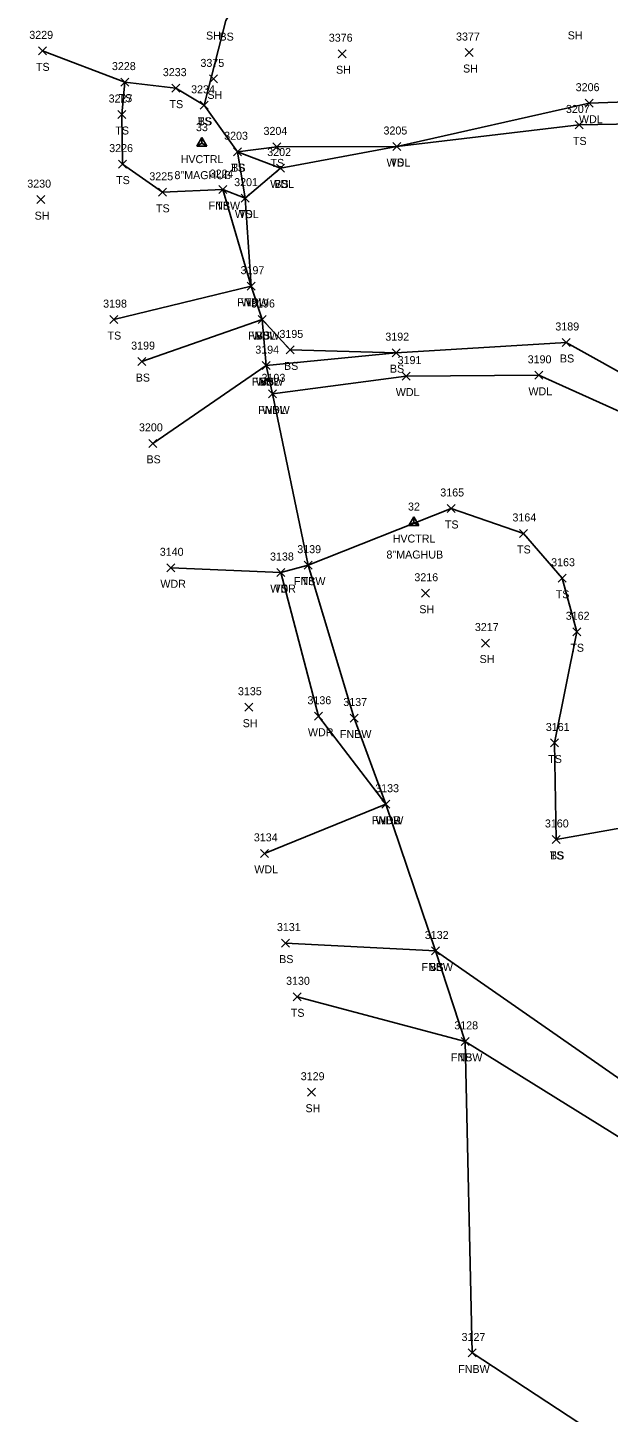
# Model space of a CAD drawing. Extents: x 1601151 to 1602912, y 499508 to 501770.
# Drawn here: x 1601337 to 1601482.2, y 500250.6 to 500596.8 of the extents above; entities that cross this region are included whole.
import ezdxf

# ---------------------------------------------------------------- set-up
doc = ezdxf.new("R2010")
doc.units = 0
for name, color, linetype in [('C_A', 7, 'Continuous'), ('C_C', 7, 'Continuous'), ('C_I', 7, 'Continuous'), ('CPSM', 7, 'Continuous'), ('L_A', 7, 'Continuous'), ('L_I', 7, 'Continuous'), ('L_TIC', 7, 'Continuous'), ('LAWA', 7, 'Continuous'), ('LELB', 7, 'Continuous'), ('LFNC', 7, 'Continuous')]:
    doc.layers.add(name, color=color, linetype=linetype)

msp = doc.modelspace()

# ---------------------------------------------------------------- linework, layer by layer
at = {"layer": 'CPSM'}
for p, q in [((1601379.29, 500567.21), (1601380.54, 500569.37)), ((1601381.79, 500567.21), (1601380.54, 500569.37)), ((1601380.54, 500567.93), (1601380.54, 500569.37)), ((1601379.29, 500567.21), (1601380.54, 500567.93)), ((1601379.29, 500567.21), (1601381.79, 500567.21)), ((1601380.54, 500567.93), (1601380.54, 500567.93)), ((1601380.54, 500567.93), (1601381.79, 500567.21)), ((1601432.31, 500472.36), (1601433.56, 500474.52)), ((1601432.31, 500472.36), (1601433.56, 500473.08)), ((1601432.31, 500472.36), (1601434.81, 500472.36)), ((1601434.81, 500472.36), (1601433.56, 500474.52)), ((1601433.56, 500473.08), (1601433.56, 500474.52)), ((1601433.56, 500473.08), (1601433.56, 500473.08)), ((1601433.56, 500473.08), (1601434.81, 500472.36))]:
    msp.add_line(p, q, dxfattribs=at)
at = {"layer": 'L_TIC'}
for points in [[(1601339.66, 500590), (1601341.66, 500592)], [(1601341.66, 500590), (1601339.66, 500592)], [(1601414.61, 500589.29), (1601416.61, 500591.29)], [(1601416.61, 500589.29), (1601414.61, 500591.29)], [(1601446.36, 500589.58), (1601448.36, 500591.58)], [(1601448.36, 500589.58), (1601446.36, 500591.58)], [(1601360.32, 500582.19), (1601362.32, 500584.19)], [(1601362.32, 500582.19), (1601360.32, 500584.19)], [(1601360.32, 500582.19), (1601362.32, 500584.19)], [(1601362.32, 500582.19), (1601360.32, 500584.19)], [(1601373.04, 500580.68), (1601375.04, 500582.68)], [(1601375.04, 500580.68), (1601373.04, 500582.68)], [(1601382.45, 500582.99), (1601384.45, 500584.99)], [(1601384.45, 500582.99), (1601382.45, 500584.99)], [(1601476.41, 500576.92), (1601478.41, 500578.92)], [(1601478.41, 500576.92), (1601476.41, 500578.92)], [(1601359.5, 500574.09), (1601361.5, 500576.09)], [(1601361.5, 500574.09), (1601359.5, 500576.09)], [(1601380.12, 500576.39), (1601382.12, 500578.39)], [(1601382.12, 500576.39), (1601380.12, 500578.39)], [(1601380.12, 500576.39), (1601382.12, 500578.39)], [(1601382.12, 500576.39), (1601380.12, 500578.39)], [(1601473.92, 500571.48), (1601475.92, 500573.48)], [(1601475.92, 500571.48), (1601473.92, 500573.48)], [(1601388.46, 500564.78), (1601390.46, 500566.78)], [(1601390.46, 500564.78), (1601388.46, 500566.78)], [(1601388.46, 500564.78), (1601390.46, 500566.78)], [(1601390.46, 500564.78), (1601388.46, 500566.78)], [(1601398.3, 500565.99), (1601400.3, 500567.99)], [(1601400.3, 500565.99), (1601398.3, 500567.99)], [(1601428.3, 500566.09), (1601430.3, 500568.09)], [(1601430.3, 500566.09), (1601428.3, 500568.09)], [(1601428.3, 500566.09), (1601430.3, 500568.09)], [(1601430.3, 500566.09), (1601428.3, 500568.09)], [(1601359.7, 500561.69), (1601361.7, 500563.69)], [(1601361.7, 500561.69), (1601359.7, 500563.69)], [(1601399.22, 500560.71), (1601401.22, 500562.71)], [(1601401.22, 500560.71), (1601399.22, 500562.71)], [(1601399.22, 500560.71), (1601401.22, 500562.71)], [(1601401.22, 500560.71), (1601399.22, 500562.71)], [(1601339.24, 500552.81), (1601341.24, 500554.81)], [(1601341.24, 500552.81), (1601339.24, 500554.81)], [(1601369.67, 500554.64), (1601371.67, 500556.64)], [(1601371.67, 500554.64), (1601369.67, 500556.64)], [(1601384.76, 500555.32), (1601386.76, 500557.32)], [(1601386.76, 500555.32), (1601384.76, 500557.32)], [(1601384.76, 500555.32), (1601386.76, 500557.32)], [(1601386.76, 500555.32), (1601384.76, 500557.32)], [(1601390.39, 500553.19), (1601392.39, 500555.19)], [(1601392.39, 500553.19), (1601390.39, 500555.19)], [(1601390.39, 500553.19), (1601392.39, 500555.19)], [(1601392.39, 500553.19), (1601390.39, 500555.19)], [(1601391.91, 500531.17), (1601393.91, 500533.17)], [(1601393.91, 500531.17), (1601391.91, 500533.17)], [(1601391.91, 500531.17), (1601393.91, 500533.17)], [(1601393.91, 500531.17), (1601391.91, 500533.17)], [(1601391.91, 500531.17), (1601393.91, 500533.17)], [(1601393.91, 500531.17), (1601391.91, 500533.17)], [(1601357.55, 500522.82), (1601359.55, 500524.82)], [(1601359.55, 500522.82), (1601357.55, 500524.82)], [(1601394.61, 500522.84), (1601396.61, 500524.84)], [(1601396.61, 500522.84), (1601394.61, 500524.84)], [(1601394.61, 500522.84), (1601396.61, 500524.84)], [(1601396.61, 500522.84), (1601394.61, 500524.84)], [(1601394.61, 500522.84), (1601396.61, 500524.84)], [(1601396.61, 500522.84), (1601394.61, 500524.84)], [(1601401.63, 500515.24), (1601403.63, 500517.24)], [(1601403.63, 500515.24), (1601401.63, 500517.24)], [(1601428.12, 500514.55), (1601430.12, 500516.55)], [(1601430.12, 500514.55), (1601428.12, 500516.55)], [(1601470.63, 500517.1), (1601472.63, 500519.1)], [(1601472.63, 500517.1), (1601470.63, 500519.1)], [(1601364.57, 500512.32), (1601366.57, 500514.32)], [(1601366.57, 500512.32), (1601364.57, 500514.32)], [(1601395.59, 500511.31), (1601397.59, 500513.31)], [(1601397.59, 500511.31), (1601395.59, 500513.31)], [(1601395.59, 500511.31), (1601397.59, 500513.31)], [(1601397.59, 500511.31), (1601395.59, 500513.31)], [(1601395.59, 500511.31), (1601397.59, 500513.31)], [(1601397.59, 500511.31), (1601395.59, 500513.31)], [(1601430.61, 500508.7), (1601432.61, 500510.7)], [(1601432.61, 500508.7), (1601430.61, 500510.7)], [(1601463.79, 500508.89), (1601465.79, 500510.89)], [(1601465.79, 500508.89), (1601463.79, 500510.89)], [(1601397.17, 500504.26), (1601399.17, 500506.26)], [(1601399.17, 500504.26), (1601397.17, 500506.26)], [(1601397.17, 500504.26), (1601399.17, 500506.26)], [(1601399.17, 500504.26), (1601397.17, 500506.26)], [(1601367.25, 500491.88), (1601369.25, 500493.88)], [(1601369.25, 500491.88), (1601367.25, 500493.88)], [(1601441.9, 500475.6), (1601443.9, 500477.6)], [(1601443.9, 500475.6), (1601441.9, 500477.6)], [(1601441.9, 500475.6), (1601443.9, 500477.6)], [(1601443.9, 500475.6), (1601441.9, 500477.6)], [(1601459.94, 500469.36), (1601461.94, 500471.36)], [(1601461.94, 500469.36), (1601459.94, 500471.36)], [(1601371.8, 500460.77), (1601373.8, 500462.77)], [(1601373.8, 500460.77), (1601371.8, 500462.77)], [(1601399.29, 500459.59), (1601401.29, 500461.59)], [(1601401.29, 500459.59), (1601399.29, 500461.59)], [(1601399.29, 500459.59), (1601401.29, 500461.59)], [(1601401.29, 500459.59), (1601399.29, 500461.59)], [(1601406.1, 500461.43), (1601408.1, 500463.43)], [(1601408.1, 500461.43), (1601406.1, 500463.43)], [(1601406.1, 500461.43), (1601408.1, 500463.43)], [(1601408.1, 500461.43), (1601406.1, 500463.43)], [(1601469.62, 500458.16), (1601471.62, 500460.16)], [(1601471.62, 500458.16), (1601469.62, 500460.16)], [(1601435.43, 500454.41), (1601437.43, 500456.41)], [(1601437.43, 500454.41), (1601435.43, 500456.41)], [(1601450.5, 500441.96), (1601452.5, 500443.96)], [(1601452.5, 500441.96), (1601450.5, 500443.96)], [(1601473.27, 500444.78), (1601475.27, 500446.78)], [(1601475.27, 500444.78), (1601473.27, 500446.78)], [(1601391.27, 500425.92), (1601393.27, 500427.92)], [(1601393.27, 500425.92), (1601391.27, 500427.92)], [(1601408.7, 500423.66), (1601410.7, 500425.66)], [(1601410.7, 500423.66), (1601408.7, 500425.66)], [(1601417.6, 500423.22), (1601419.6, 500425.22)], [(1601419.6, 500423.22), (1601417.6, 500425.22)], [(1601467.73, 500416.98), (1601469.73, 500418.98)], [(1601469.73, 500416.98), (1601467.73, 500418.98)], [(1601425.58, 500401.67), (1601427.58, 500403.67)], [(1601427.58, 500401.67), (1601425.58, 500403.67)], [(1601425.58, 500401.67), (1601427.58, 500403.67)], [(1601427.58, 500401.67), (1601425.58, 500403.67)], [(1601425.58, 500401.67), (1601427.58, 500403.67)], [(1601427.58, 500401.67), (1601425.58, 500403.67)], [(1601468.15, 500392.86), (1601470.15, 500394.86)], [(1601470.15, 500392.86), (1601468.15, 500394.86)], [(1601468.15, 500392.86), (1601470.15, 500394.86)], [(1601470.15, 500392.86), (1601468.15, 500394.86)], [(1601395.23, 500389.38), (1601397.23, 500391.38)], [(1601397.23, 500389.38), (1601395.23, 500391.38)], [(1601400.43, 500366.95), (1601402.43, 500368.95)], [(1601402.43, 500366.95), (1601400.43, 500368.95)], [(1601437.99, 500364.98), (1601439.99, 500366.98)], [(1601439.99, 500364.98), (1601437.99, 500366.98)], [(1601437.99, 500364.98), (1601439.99, 500366.98)], [(1601439.99, 500364.98), (1601437.99, 500366.98)], [(1601403.37, 500353.52), (1601405.37, 500355.52)], [(1601405.37, 500353.52), (1601403.37, 500355.52)], [(1601445.35, 500342.38), (1601447.35, 500344.38)], [(1601447.35, 500342.38), (1601445.35, 500344.38)], [(1601445.35, 500342.38), (1601447.35, 500344.38)], [(1601447.35, 500342.38), (1601445.35, 500344.38)], [(1601406.97, 500329.67), (1601408.97, 500331.67)], [(1601408.97, 500329.67), (1601406.97, 500331.67)], [(1601447.17, 500264.48), (1601449.17, 500266.48)], [(1601449.17, 500264.48), (1601447.17, 500266.48)]]:
    msp.add_lwpolyline(points, dxfattribs=at)
at = {"layer": 'LAWA'}
for points in [[(1601544.34, 500325.67), (1601519.22, 500363.44), (1601505.75, 500400.34), (1601520.62, 500411.67), (1601500.1, 500494.02), (1601464.79, 500509.89), (1601431.61, 500509.7), (1601398.17, 500505.26), (1601396.59, 500512.31), (1601395.61, 500523.84), (1601392.91, 500532.17), (1601391.39, 500554.19), (1601400.22, 500561.71), (1601429.3, 500567.09), (1601477.41, 500577.92), (1601523.77, 500579.55), (1601560.2, 500571.77), (1601556.37, 500545), (1601575.25, 500522.25), (1601572.33, 500557.32), (1601570.48, 500566.05)], [(1601426.58, 500402.67), (1601409.7, 500424.66), (1601400.29, 500460.59), (1601372.8, 500461.77)], [(1601426.58, 500402.67), (1601396.23, 500390.38)]]:
    msp.add_lwpolyline(points, dxfattribs=at)
at = {"layer": 'LELB'}
for points in [[(1601400.22, 500561.71), (1601389.46, 500565.78), (1601381.12, 500577.39), (1601386.5, 500598.56), (1601395.6, 500613.55), (1601414.62, 500625.07), (1601439.1, 500619.46), (1601474.92, 500625.17)], [(1601385.76, 500556.32), (1601370.67, 500555.64), (1601360.7, 500562.69), (1601360.5, 500575.09), (1601361.32, 500583.19), (1601340.66, 500591)], [(1601361.32, 500583.19), (1601374.04, 500581.68), (1601381.12, 500577.39)], [(1601391.39, 500554.19), (1601389.46, 500565.78), (1601399.3, 500566.99), (1601429.3, 500567.09), (1601474.92, 500572.48), (1601521.56, 500573.33), (1601560.2, 500571.77), (1601571.6, 500572.54), (1601583.23, 500572.75), (1601587.85, 500570.12), (1601597.03, 500565.28), (1601591.65, 500558.79)], [(1601391.39, 500554.19), (1601385.76, 500556.32)], [(1601392.91, 500532.17), (1601358.55, 500523.82)], [(1601402.63, 500516.24), (1601395.61, 500523.84), (1601365.57, 500513.32)], [(1601505.75, 500400.34), (1601529.2, 500405.62), (1601546.77, 500411.94), (1601552.89, 500447.21), (1601530.6, 500483.27), (1601555.01, 500494.39), (1601547.11, 500513.14), (1601509.53, 500496.99), (1601471.63, 500518.1), (1601429.12, 500515.55), (1601396.59, 500512.31), (1601368.25, 500492.88)], [(1601402.63, 500516.24), (1601429.12, 500515.55)], [(1601400.29, 500460.59), (1601407.1, 500462.43), (1601442.9, 500476.6)], [(1601469.15, 500393.86), (1601468.73, 500417.98), (1601474.27, 500445.78), (1601470.62, 500459.16), (1601460.94, 500470.36), (1601442.9, 500476.6)], [(1601505.75, 500400.34), (1601469.15, 500393.86)], [(1601401.43, 500367.95), (1601438.99, 500365.98), (1601491.06, 500329.76), (1601544.34, 500325.67)], [(1601608.13, 500275.28), (1601543.25, 500306.85), (1601488.66, 500317.14), (1601446.35, 500343.38), (1601404.37, 500354.52)]]:
    msp.add_lwpolyline(points, dxfattribs=at)
at = {"layer": 'LFNC'}
msp.add_lwpolyline([(1601630.4, 500172), (1601539.57, 500215.59), (1601496.11, 500234.02), (1601448.17, 500265.48), (1601446.35, 500343.38), (1601438.99, 500365.98), (1601426.58, 500402.67), (1601418.6, 500424.22), (1601407.1, 500462.43), (1601398.17, 500505.26), (1601396.59, 500512.31), (1601395.61, 500523.84), (1601392.91, 500532.17), (1601385.76, 500556.32)], dxfattribs=at)

# ---------------------------------------------------------------- texts
at = {"layer": 'C_A'}
for p in [(1601375.24, 500562.93), (1601428.25, 500468.08)]:
    msp.add_text('HVCTRL', height=2, dxfattribs=at).set_placement(p)
at = {"layer": 'C_C'}
for p in [(1601373.69, 500558.93), (1601426.7, 500464.08)]:
    msp.add_text('8"MAGHUB', height=2, dxfattribs=at).set_placement(p)
at = {"layer": 'C_I'}
for s, p in [('33', (1601379.08, 500570.93)), ('32', (1601432.09, 500476.08))]:
    msp.add_text(s, height=2, dxfattribs=at).set_placement(p)
at = {"layer": 'L_A'}
for s, p in [('SH', (1601472.01, 500593.87)), ('SH', (1601381.58, 500593.82)), ('BS', (1601384.95, 500593.56)), ('TS', (1601339.07, 500586)), ('SH', (1601414.09, 500585.29)), ('SH', (1601445.85, 500585.58)), ('TS', (1601359.73, 500578.19)), ('TS', (1601359.73, 500578.19)), ('TS', (1601372.45, 500576.68)), ('SH', (1601381.94, 500578.99)), ('TS', (1601358.91, 500570.09)), ('TS', (1601379.53, 500572.39)), ('BS', (1601379.56, 500572.39)), ('WDL', (1601474.83, 500572.92)), ('TS', (1601473.33, 500567.48)), ('TS', (1601387.87, 500560.78)), ('BS', (1601387.9, 500560.78)), ('TS', (1601397.7, 500561.99)), ('WDL', (1601426.72, 500562.09)), ('TS', (1601427.71, 500562.09)), ('TS', (1601359.1, 500557.69)), ('WDL', (1601397.64, 500556.71)), ('BS', (1601398.67, 500556.71)), ('TS', (1601369.08, 500550.64)), ('FNBW', (1601382.23, 500551.32)), ('TS', (1601384.17, 500551.32)), ('WDL', (1601388.81, 500549.19)), ('TS', (1601389.8, 500549.19)), ('SH', (1601338.73, 500548.81)), ('FNBW', (1601389.38, 500527.17)), ('WDL', (1601390.33, 500527.17)), ('TS', (1601391.32, 500527.17)), ('TS', (1601356.96, 500518.82)), ('FNBW', (1601392.08, 500518.84)), ('WDL', (1601393.03, 500518.84)), ('BS', (1601394.05, 500518.84)), ('BS', (1601401.08, 500511.24)), ('BS', (1601470.07, 500513.1)), ('BS', (1601364.01, 500508.32)), ('BS', (1601395.03, 500507.31)), ('BS', (1601427.56, 500510.55)), ('FNBW', (1601393.06, 500507.31)), ('WDL', (1601394.01, 500507.31)), ('WDL', (1601429.03, 500504.7)), ('WDL', (1601462.2, 500504.89)), ('FNBW', (1601394.64, 500500.26)), ('WDL', (1601395.58, 500500.26)), ('BS', (1601366.69, 500487.88)), ('TS', (1601441.31, 500471.6)), ('TS', (1601441.31, 500471.6)), ('TS', (1601459.35, 500465.36)), ('WDR', (1601370.17, 500456.77)), ('WDR', (1601397.65, 500455.59)), ('TS', (1601398.7, 500455.59)), ('FNBW', (1601403.57, 500457.43)), ('TS', (1601405.51, 500457.43)), ('TS', (1601469.03, 500454.16)), ('SH', (1601434.92, 500450.41)), ('TS', (1601472.68, 500440.78)), ('SH', (1601449.99, 500437.96)), ('SH', (1601390.75, 500421.92)), ('WDR', (1601407.06, 500419.66)), ('FNBW', (1601415.07, 500419.22)), ('TS', (1601467.14, 500412.98)), ('FNBW', (1601423.06, 500397.67)), ('WDR', (1601423.95, 500397.67)), ('WDL', (1601424, 500397.67)), ('TS', (1601467.56, 500388.86)), ('BS', (1601467.59, 500388.86)), ('WDL', (1601393.65, 500385.38)), ('BS', (1601399.87, 500362.95)), ('FNBW', (1601435.46, 500360.98)), ('BS', (1601437.43, 500360.98)), ('TS', (1601402.78, 500349.52)), ('FNBW', (1601442.82, 500338.38)), ('TS', (1601444.76, 500338.38)), ('SH', (1601406.46, 500325.67)), ('FNBW', (1601444.64, 500260.48))]:
    msp.add_text(s, height=2, dxfattribs=at).set_placement(p)
at = {"layer": 'L_I'}
for s, p in [('3229', (1601337.4, 500594)), ('3376', (1601412.29, 500593.29)), ('3377', (1601444.1, 500593.58)), ('3375', (1601380.19, 500586.99)), ('3228', (1601358.06, 500586.19)), ('3228', (1601358.06, 500586.19)), ('3233', (1601370.78, 500584.68)), ('3234', (1601377.86, 500580.39)), ('3234', (1601377.86, 500580.39)), ('3206', (1601474.02, 500580.92)), ('3227', (1601357.24, 500578.09)), ('3207', (1601471.58, 500575.48)), ('3204', (1601395.96, 500569.99)), ('3205', (1601425.96, 500570.09)), ('3205', (1601425.96, 500570.09)), ('3203', (1601386.12, 500568.78)), ('3203', (1601386.12, 500568.78)), ('3226', (1601357.38, 500565.69)), ('3202', (1601396.89, 500564.71)), ('3202', (1601396.89, 500564.71)), ('3224', (1601382.5, 500559.32)), ('3224', (1601382.5, 500559.32)), ('3230', (1601336.89, 500556.81)), ('3225', (1601367.41, 500558.64)), ('3201', (1601388.62, 500557.19)), ('3201', (1601388.62, 500557.19)), ('3197', (1601390.22, 500535.17)), ('3197', (1601390.22, 500535.17)), ('3197', (1601390.22, 500535.17)), ('3198', (1601355.86, 500526.82)), ('3196', (1601392.86, 500526.84)), ('3196', (1601392.86, 500526.84)), ('3196', (1601392.86, 500526.84)), ('3195', (1601399.94, 500519.24)), ('3192', (1601426.42, 500518.55)), ('3189', (1601468.93, 500521.1)), ('3199', (1601362.87, 500516.32)), ('3194', (1601393.9, 500515.31)), ('3194', (1601393.9, 500515.31)), ('3194', (1601393.9, 500515.31)), ('3191', (1601429.49, 500512.7)), ('3190', (1601462.01, 500512.89)), ('3193', (1601395.47, 500508.26)), ('3193', (1601395.47, 500508.26)), ('3200', (1601364.82, 500495.88)), ('3165', (1601440.16, 500479.6)), ('3165', (1601440.16, 500479.6)), ('3164', (1601458.2, 500473.36)), ('3140', (1601370.02, 500464.77)), ('3138', (1601397.59, 500463.59)), ('3138', (1601397.59, 500463.59)), ('3139', (1601404.4, 500465.43)), ('3139', (1601404.4, 500465.43)), ('3163', (1601467.88, 500462.16)), ('3216', (1601433.68, 500458.41)), ('3162', (1601471.53, 500448.78)), ('3217', (1601448.81, 500445.96)), ('3135', (1601389.57, 500429.92)), ('3136', (1601406.95, 500427.66)), ('3137', (1601415.91, 500427.22)), ('3161', (1601466.55, 500420.98)), ('3133', (1601423.89, 500405.67)), ('3133', (1601423.89, 500405.67)), ('3133', (1601423.89, 500405.67)), ('3160', (1601466.32, 500396.86)), ('3160', (1601466.32, 500396.86)), ('3134', (1601393.54, 500393.38)), ('3131', (1601399.31, 500370.95)), ('3132', (1601436.29, 500368.98)), ('3132', (1601436.29, 500368.98)), ('3130', (1601401.6, 500357.52)), ('3128', (1601443.66, 500346.38)), ('3128', (1601443.66, 500346.38)), ('3129', (1601405.27, 500333.67)), ('3127', (1601445.48, 500268.48))]:
    msp.add_text(s, height=2, dxfattribs=at).set_placement(p)

doc.saveas('drawing.dxf')
